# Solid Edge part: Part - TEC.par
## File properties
Author: hhakima
Template: Normal.par
Last saved by: hhakima
Revision: 5
Application: Solid Edge
Density: 2712.000 kg/m^3
Accuracy: 0.990
Material: Aluminum, 6061-T6
Face Style: Aluminum
Fill Style: ANSI38(Aluminum)
Virtual Style: Polished aluminum
Coef. of Thermal Exp: 2.3e-05
Thermal Conductivity: 180.0
Specific Heat: 920.0
Modulus of Elasticity: 68947570000.0
Poission's Ratio: 0.33
Yield Stress: 275790280.0
Ultimate Stress: 310264065.0
Elongation: 0.0
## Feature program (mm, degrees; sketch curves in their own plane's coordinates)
sketch for "unnamed Protrusion 1" plane through (0, 0, 0) normal (0, 0, 1) x-axis (1, 0, 0)
  circle centre (0, 0) radius 7.25
extrude "unnamed Protrusion 1" add finite 0.5 along +normal
sketch for "ExtrudedProtrusion_2" plane through (0, 0, 0.5) normal (0, 0, 1) x-axis (1, 0, 0)
  circle centre (0, 0) radius 5
extrude "ExtrudedProtrusion_2" add finite 1.8 along +normal
sketch for "ExtrudedProtrusion_3" plane through (0, 0, 2.3) normal (0, 0, 1) x-axis (1, 0, 0)
  circle centre (0, 0) radius 7.25
extrude "ExtrudedProtrusion_3" add finite 0.5 along +normal
sketch for "unnamed Cutout 1" plane through (0, 0, 2.8) normal (0, 0, 1) x-axis (0, 1, 0)
  circle centre (0, 0) radius 2
extrude "unnamed Cutout 1" cut to key point along -normal
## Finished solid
Body 1: solid body, 8 faces, 8 edges, 0 vertices.
  Faces by surface: cylinder 4, plane 4
  Edges by curve: circle 8
Bounding box of the edges (mm): 14.500 x 14.500 x 2.800, from (-7.25, -7.25, 0) to (7.25, 7.25, 2.8).
Cylindrical faces by radius (mm): R2 x1, R5 x1, R7.25 x2
Planar faces by outward normal: +z 2, -z 2
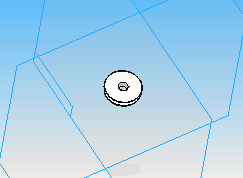
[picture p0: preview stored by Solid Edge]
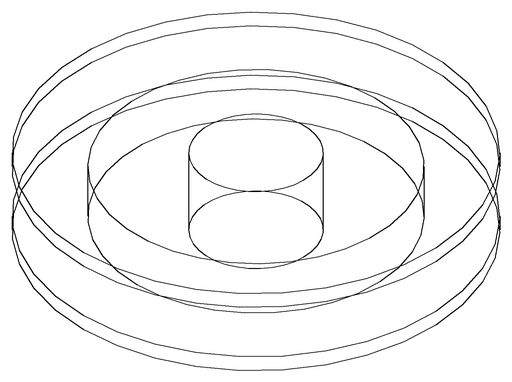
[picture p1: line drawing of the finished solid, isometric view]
